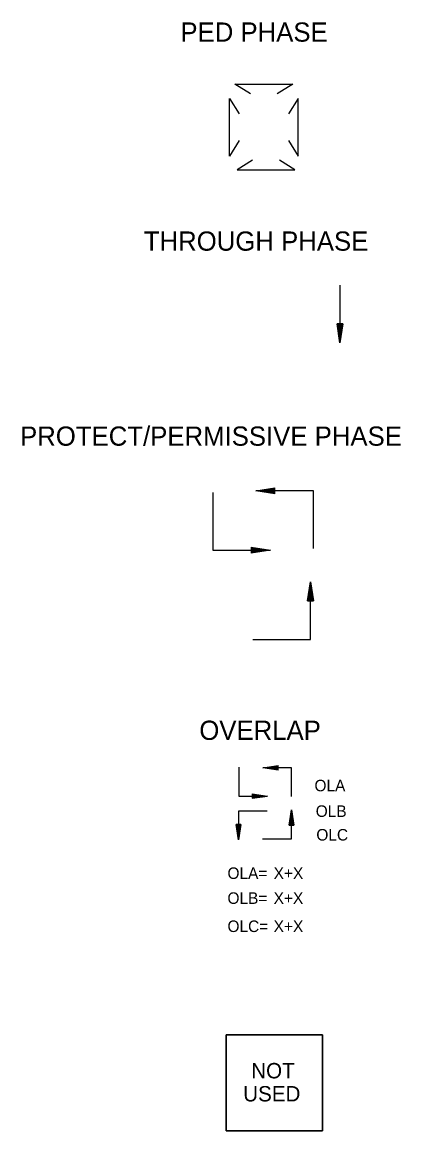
# Model space of a CAD drawing. Extents: x 1736833 to 1738623, y 544707 to 545544.
# Drawn here: x 1736833.2 to 1736931.5, y 545255.7 to 545543.9 of the extents above; entities that cross this region are included whole.
import ezdxf

# ---------------------------------------------------------------- set-up
doc = ezdxf.new("R2010")
doc.units = 0
doc.layers.add('R_Draft', color=7, linetype='Continuous')
doc.layers.add('T_Drafting', color=7, linetype='Continuous')

msp = doc.modelspace()

# ---------------------------------------------------------------- linework, layer by layer
at = {"layer": 'R_Draft'}
for p, q in [((1736892.94, 545343.32), (1736896.94, 545342.72)), ((1736892.94, 545343.32), (1736892.94, 545342.12)), ((1736892.94, 545343.22), (1736896.27, 545342.72)), ((1736892.94, 545343.12), (1736895.58, 545342.72)), ((1736892.94, 545343.02), (1736894.92, 545342.72)), ((1736892.94, 545342.92), (1736894.24, 545342.72)), ((1736892.94, 545342.82), (1736893.57, 545342.72)), ((1736892.94, 545342.12), (1736896.94, 545342.72)), ((1736892.94, 545342.53), (1736894.24, 545342.72)), ((1736892.94, 545342.33), (1736895.58, 545342.72)), ((1736892.94, 545342.22), (1736896.27, 545342.72)), ((1736892.94, 545342.43), (1736894.92, 545342.72)), ((1736892.94, 545342.63), (1736893.57, 545342.72))]:
    msp.add_line(p, q, dxfattribs=at)
at = {"layer": 'T_Drafting'}
for p, q in [((1736915.74, 545475.49), (1736915.74, 545460.49)), ((1736915.74, 545460.49), (1736914.99, 545465.49)), ((1736916.49, 545465.49), (1736914.99, 545465.49)), ((1736915.12, 545465.49), (1736915.74, 545461.32)), ((1736915.74, 545462.18), (1736915.25, 545465.49)), ((1736915.37, 545465.49), (1736915.74, 545463.01)), ((1736915.74, 545463.86), (1736915.5, 545465.49)), ((1736915.63, 545465.49), (1736915.74, 545464.7)), ((1736915.74, 545464.7), (1736915.86, 545465.49)), ((1736915.99, 545465.49), (1736915.74, 545463.86)), ((1736915.74, 545463.01), (1736916.12, 545465.49)), ((1736916.24, 545465.49), (1736915.74, 545462.18)), ((1736915.74, 545461.32), (1736916.37, 545465.49)), ((1736916.49, 545465.49), (1736915.74, 545460.49)), ((1736893.85, 545422.06), (1736898.85, 545422.81)), ((1736898.85, 545422.69), (1736894.69, 545422.06)), ((1736895.55, 545422.06), (1736898.85, 545422.56)), ((1736898.85, 545422.43), (1736896.38, 545422.06)), ((1736897.23, 545422.06), (1736898.85, 545422.31)), ((1736898.85, 545422.18), (1736898.06, 545422.06)), ((1736898.85, 545421.31), (1736898.85, 545422.81)), ((1736882.67, 545421.64), (1736882.67, 545406.64)), ((1736908.85, 545422.06), (1736893.85, 545422.06)), ((1736898.85, 545421.31), (1736893.85, 545422.06)), ((1736894.69, 545422.06), (1736898.85, 545421.44)), ((1736898.85, 545421.56), (1736895.55, 545422.06)), ((1736896.38, 545422.06), (1736898.85, 545421.69)), ((1736898.85, 545421.82), (1736897.23, 545422.06)), ((1736898.06, 545422.06), (1736898.85, 545421.94)), ((1736908.85, 545407.06), (1736908.85, 545422.06)), ((1736882.67, 545406.64), (1736897.67, 545406.64)), ((1736892.67, 545407.39), (1736897.67, 545406.64)), ((1736892.67, 545407.39), (1736892.67, 545405.89)), ((1736896.84, 545406.64), (1736892.67, 545407.26)), ((1736892.67, 545407.14), (1736895.98, 545406.64)), ((1736895.15, 545406.64), (1736892.67, 545407.01)), ((1736892.67, 545406.88), (1736894.3, 545406.64)), ((1736893.46, 545406.64), (1736892.67, 545406.76)), ((1736897.67, 545406.64), (1736892.67, 545405.89)), ((1736892.67, 545406.01), (1736896.84, 545406.64)), ((1736895.98, 545406.64), (1736892.67, 545406.14)), ((1736892.67, 545406.27), (1736895.15, 545406.64)), ((1736894.3, 545406.64), (1736892.67, 545406.39)), ((1736892.67, 545406.52), (1736893.46, 545406.64)), ((1736907.34, 545393.42), (1736908.09, 545398.42)), ((1736908.09, 545397.59), (1736907.47, 545393.42)), ((1736907.6, 545393.42), (1736908.09, 545396.73)), ((1736908.09, 545383.42), (1736908.09, 545398.42)), ((1736908.09, 545398.42), (1736908.84, 545393.42)), ((1736908.72, 545393.42), (1736908.09, 545397.59)), ((1736908.09, 545396.73), (1736908.59, 545393.42)), ((1736907.34, 545393.42), (1736908.84, 545393.42)), ((1736908.09, 545395.89), (1736907.72, 545393.42)), ((1736907.85, 545393.42), (1736908.09, 545395.05)), ((1736908.09, 545394.21), (1736907.98, 545393.42)), ((1736908.47, 545393.42), (1736908.09, 545395.89)), ((1736908.09, 545395.05), (1736908.34, 545393.42)), ((1736908.21, 545393.42), (1736908.09, 545394.21)), ((1736893.09, 545383.42), (1736908.09, 545383.42)), ((1736889.44, 545350.22), (1736889.44, 545342.72)), ((1736895.67, 545350.06), (1736899.67, 545350.66)), ((1736899.67, 545350.56), (1736896.33, 545350.06)), ((1736897.02, 545350.06), (1736899.67, 545350.46)), ((1736899.67, 545350.36), (1736897.69, 545350.06)), ((1736898.37, 545350.06), (1736899.67, 545350.26)), ((1736899.67, 545350.15), (1736899.03, 545350.06)), ((1736899.67, 545349.46), (1736899.67, 545350.66)), ((1736903.17, 545350.06), (1736895.67, 545350.06)), ((1736899.67, 545349.46), (1736895.67, 545350.06)), ((1736896.33, 545350.06), (1736899.67, 545349.56)), ((1736899.67, 545349.66), (1736897.02, 545350.06)), ((1736897.69, 545350.06), (1736899.67, 545349.76)), ((1736899.67, 545349.87), (1736898.37, 545350.06)), ((1736899.03, 545350.06), (1736899.67, 545349.97)), ((1736903.17, 545342.56), (1736903.17, 545350.06)), ((1736889.44, 545342.72), (1736896.94, 545342.72)), ((1736892.94, 545343.32), (1736896.94, 545342.72)), ((1736892.94, 545343.32), (1736892.94, 545342.12)), ((1736896.27, 545342.72), (1736892.94, 545343.22)), ((1736892.94, 545343.12), (1736895.58, 545342.72)), ((1736894.92, 545342.72), (1736892.94, 545343.02)), ((1736892.94, 545342.92), (1736894.24, 545342.72)), ((1736893.57, 545342.72), (1736892.94, 545342.82)), ((1736896.94, 545342.72), (1736892.94, 545342.12)), ((1736892.94, 545342.22), (1736896.27, 545342.72)), ((1736895.58, 545342.72), (1736892.94, 545342.33)), ((1736892.94, 545342.43), (1736894.92, 545342.72)), ((1736894.24, 545342.72), (1736892.94, 545342.53)), ((1736892.94, 545342.63), (1736893.57, 545342.72)), ((1736896.86, 545338.82), (1736889.36, 545338.82)), ((1736889.36, 545338.82), (1736889.36, 545331.32)), ((1736902.54, 545335.11), (1736903.14, 545339.11)), ((1736903.14, 545331.61), (1736903.14, 545339.11)), ((1736903.14, 545339.11), (1736903.74, 545335.11)), ((1736903.14, 545338.44), (1736902.64, 545335.11)), ((1736902.74, 545335.11), (1736903.14, 545337.75)), ((1736903.14, 545337.08), (1736902.84, 545335.11)), ((1736902.95, 545335.11), (1736903.14, 545336.41)), ((1736903.14, 545335.74), (1736903.05, 545335.11)), ((1736903.64, 545335.11), (1736903.14, 545338.44)), ((1736903.14, 545337.75), (1736903.54, 545335.11)), ((1736903.44, 545335.11), (1736903.14, 545337.08)), ((1736903.14, 545336.41), (1736903.34, 545335.11)), ((1736903.24, 545335.11), (1736903.14, 545335.74)), ((1736889.36, 545331.32), (1736888.76, 545335.32)), ((1736889.96, 545335.32), (1736888.76, 545335.32)), ((1736888.86, 545335.32), (1736889.36, 545331.99)), ((1736889.36, 545332.68), (1736888.96, 545335.32)), ((1736889.06, 545335.32), (1736889.36, 545333.34)), ((1736889.36, 545334.02), (1736889.16, 545335.32)), ((1736889.27, 545335.32), (1736889.36, 545334.69)), ((1736889.36, 545334.69), (1736889.45, 545335.32)), ((1736889.55, 545335.32), (1736889.36, 545334.02)), ((1736889.36, 545333.34), (1736889.66, 545335.32)), ((1736889.76, 545335.32), (1736889.36, 545332.68)), ((1736889.36, 545331.99), (1736889.86, 545335.32)), ((1736889.96, 545335.32), (1736889.36, 545331.32)), ((1736902.54, 545335.11), (1736903.74, 545335.11)), ((1736895.64, 545331.61), (1736903.14, 545331.61)), ((1736886.16, 545280.68), (1736886.16, 545255.68)), ((1736911.16, 545280.68), (1736886.16, 545280.68)), ((1736911.16, 545255.68), (1736911.16, 545280.68)), ((1736886.16, 545255.68), (1736911.16, 545255.68))]:
    msp.add_line(p, q, dxfattribs=at)
for points in [[(1736892.45, 545525.26), (1736888.45, 545527.76), (1736903.45, 545527.76), (1736899.45, 545525.26)], [(1736889.52, 545513.09), (1736887.02, 545509.09), (1736887.02, 545524.09), (1736889.52, 545520.09)], [(1736902.4, 545513.09), (1736904.9, 545509.09), (1736904.9, 545524.09), (1736902.4, 545520.09)], [(1736893.02, 545507.99), (1736889.02, 545505.49), (1736904.02, 545505.49), (1736900.02, 545507.99)]]:
    msp.add_lwpolyline(points, dxfattribs=at)
msp.add_lwpolyline([(1736886.16, 545280.68), (1736911.16, 545280.68), (1736911.16, 545255.68), (1736886.16, 545255.68)], close=True, dxfattribs=at)

# ---------------------------------------------------------------- texts
for s, height, p in [('PED PHASE', 5, (1736874.28, 545538.82)), ('THROUGH PHASE', 5, (1736864.78, 545484.48)), ('PROTECT/PERMISSIVE PHASE', 5, (1736832.63, 545433.78)), ('OVERLAP', 5, (1736879.19, 545357.31)), ('OLA', 3, (1736909.11, 545343.94)), ('OLB', 3, (1736909.44, 545337.29)), ('OLC', 3, (1736909.6, 545331.14)), ('OLA=', 3, (1736886.51, 545321.16)), ('X+X', 3, (1736898.51, 545321.16)), ('OLB=', 3, (1736886.51, 545314.68)), ('X+X', 3, (1736898.51, 545314.68)), ('OLC=', 3, (1736886.51, 545307.36)), ('X+X', 3, (1736898.51, 545307.36)), ('NOT', 4, (1736892.68, 545269.32)), ('USED', 4, (1736890.6, 545263.32))]:
    msp.add_text(s, height=height, dxfattribs=at).set_placement(p)

doc.saveas('drawing.dxf')
